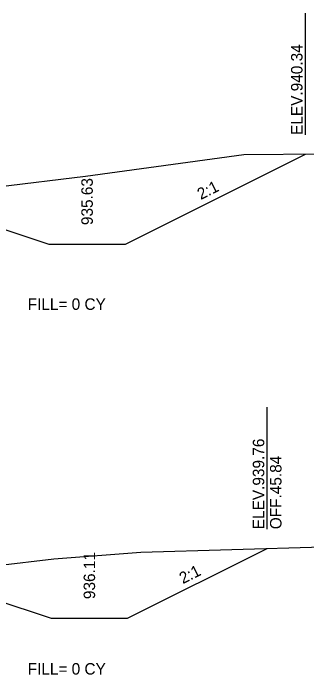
# Model space of a CAD drawing. Extents: x -4 to 359, y 0 to 1436.
# Drawn here: x 285.07 to 300.41, y 798.14 to 832.66 of the extents above; entities that cross this region are included whole.
import ezdxf

# ---------------------------------------------------------------- set-up
doc = ezdxf.new("R2010")
doc.units = 0
for name, color, linetype in [('XS-Existing surface-ground', 7, 'Continuous'), ('XS-Proposed surface-ground', 7, 'Continuous'), ('XS-Text-ditch slope', 7, 'Continuous'), ('XS-Text-earthwork labels', 7, 'Continuous'), ('XS-Text-profile report', 7, 'Continuous'), ('XS-Text-tie elevation', 7, 'Continuous'), ('XS-Text-tie offset', 7, 'Continuous')]:
    doc.layers.add(name, color=color, linetype=linetype)

msp = doc.modelspace()

# ---------------------------------------------------------------- linework, layer by layer
at = {"layer": 'XS-Existing surface-ground'}
for p, q in [((297.129, 825.292), (322.4, 825.452)), ((288.85, 824.161), (297.129, 825.292)), ((278.799, 822.939), (288.85, 824.161)), ((291.732, 804.536), (301.328, 804.826)), ((287.186, 804.193), (291.732, 804.536)), ((275.985, 802.839), (287.186, 804.193))]:
    msp.add_line(p, q, dxfattribs=at)
at = {"layer": 'XS-Proposed surface-ground'}
for points in [[(280.928, 822.587), (286.928, 820.607), (290.928, 820.607), (300.338, 825.313)], [(281.048, 803.07), (287.048, 801.09), (291.048, 801.09), (298.339, 804.736)]]:
    msp.add_lwpolyline(points, dxfattribs=at)
at = {"layer": 'XS-Text-tie offset'}
for p, q in [((300.338, 826.313), (300.338, 832.663)), ((298.339, 805.736), (298.339, 812.114))]:
    msp.add_line(p, q, dxfattribs=at)

# ---------------------------------------------------------------- texts
at = {"layer": 'XS-Text-ditch slope'}
for p in [(294.873, 822.915), (293.933, 802.868)]:
    msp.add_text('2:1', height=0.6, rotation=26.5651, dxfattribs=at).set_placement(p)
at = {"layer": 'XS-Text-earthwork labels'}
for p in [(285.826, 817.183), (285.826, 798.15)]:
    msp.add_text('FILL= 0 CY           ', height=0.6, dxfattribs=at).set_placement(p)
at = {"layer": 'XS-Text-profile report'}
for s, p in [('Dtch_Bkslp_1_T', (300.327, 825.312)), ('Dtch_Frslp_1_B', (286.917, 820.607)), ('Dtch_Bkslp_1_B', (290.917, 820.607)), ('Dtch_Bkslp_1_T', (298.327, 804.735)), ('Dtch_Frslp_1_B', (287.036, 801.089)), ('Dtch_Bkslp_1_B', (291.036, 801.089))]:
    msp.add_text(s, height=0.00167, dxfattribs=at).set_placement(p)
at = {"layer": 'XS-Text-tie elevation'}
for s, p in [('ELEV.940.34', (300.188, 826.313)), ('935.63', (289.228, 821.607)), ('ELEV.939.76', (298.189, 805.736)), ('OFF.45.84', (299.089, 805.736)), ('936.11', (289.348, 802.09))]:
    msp.add_text(s, height=0.6, rotation=90, dxfattribs=at).set_placement(p)

doc.saveas('drawing.dxf')
